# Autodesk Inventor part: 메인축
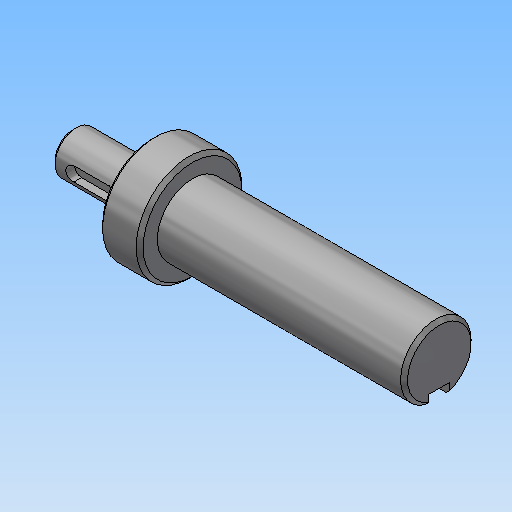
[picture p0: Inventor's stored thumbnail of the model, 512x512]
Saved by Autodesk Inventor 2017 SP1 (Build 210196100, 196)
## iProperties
Created: 2018-09
Part Number: 메인축
Document SubType Name: Modeling
Density: 1 g/cm^3
Material: 강철, 연강
Appearance: 강철
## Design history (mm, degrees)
sketch "스케치1"
  geometry: L1 (34.997, -37.5)-(34.997, -77.5) reference; L2 (46.5, -38.401)-(46.5, -76.599) reference; L3 (12.497, -57.5)-(116.5, -57.5); L4 (12.497, -63.5)-(34.997, -63.5); L5 (34.997, -72.5)-(46.5, -72.5); L6 (46.5, -67.5)-(116.5, -67.5); L7 (116.5, -67.5)-(116.5, -57.5); L8 (12.497, -63.5)-(12.497, -57.5); 2 further points
  constraints: 12 end point, 5 point on line, 4 perpendicular, 1 midpoint, 1 parallel
  dimensions: "d0" = 20 diameter of L6 L3; "d1" = 30 diameter of L5 L3; "d2" = 22.5 distance of L4.start L4.end; "d3" = 70 distance of L6.start L6.end; "d5" = 12 diameter of L4 L3
revolve "회전1" sketch "스케치1" stored, may be unused: angle "d4" = 90 deg
chamfer "모따기1" distance "d6" = 1; stored, may be unused: second distance "d7" = 2, angle "d8" = 45 deg
node "작업 평면1"
sketch "스케치2"
  geometry: L1 (-11.25, -5)-(-11.25, 5) reference; L2 (-5.25, 2)-(4.75, 2); L3 (4.75, -2)-(-5.25, -2); A1 r 2 centre (4.75, 0) between (4.75, -2) and (4.75, 2); A2 r 2 centre (-5.25, 0) between (-5.25, 2) and (-5.25, -2); 2 further points
  constraints: 4 end point, 4 point on circle, 4 tangent, 2 centre point, 1 horizontal alignment, 1 midpoint, 1 parallel, 1 perpendicular
  dimensions: "d9" = 4 distance between parallel lines of L3 L2; "d10" = 14 dimension on A1 A2; "d11" = 4 distance edge to line of A2 L1
extrude "돌출1" cut sketch "스케치2" distance "d12" = 2.5; taper "d13" = 0 deg
node "작업 평면2"
sketch "스케치3"
  geometry: L1 (35, 9)-(35, -9) reference; L2 (35, 3)-(20, 3); L3 (20, -3)-(35, -3); A1 r 3 centre (20, 0) between (20, 3) and (20, -3); 2 further points
  constraints: 4 end point, 2 perpendicular, 2 point on circle, 2 point on line, 2 tangent, 1 centre point, 1 horizontal alignment, 1 midpoint
  dimensions: "d14" = 6 distance between parallel lines of L3 L2; "d15" = 18 dimension on A1 L1
extrude "돌출2" cut sketch "스케치3" distance "d16" = 3.5; taper "d17" = 0 deg
node "솔리드1"
node "참조1"
node "참조2"
